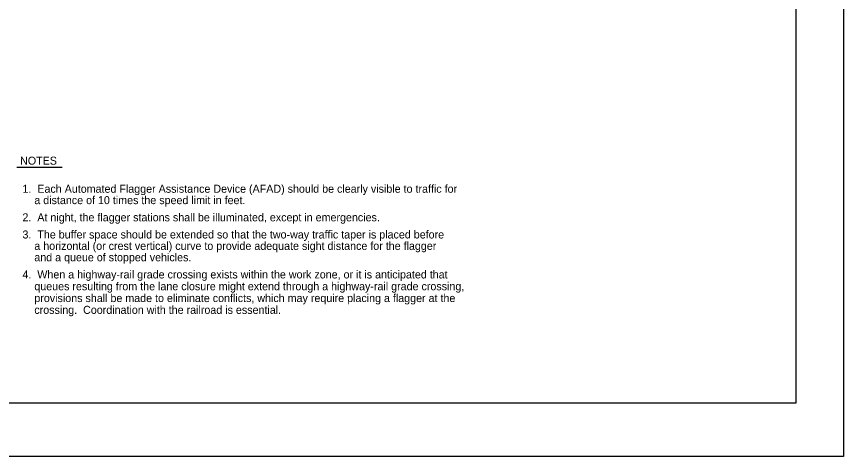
# Model space of a CAD drawing. Extents: x -14145 to -13662, y 30244 to 30661.
# Drawn here: x -13812.88 to -13791.17, y 30478.81 to 30490.36 of the extents above; entities that cross this region are included whole.
import ezdxf

# ---------------------------------------------------------------- set-up
doc = ezdxf.new("R2010")
doc.units = 0
for name, color, linetype in [('10', 7, 'Continuous'), ('2', 7, 'Continuous'), ('61', 7, 'Continuous')]:
    doc.layers.add(name, color=color, linetype=linetype)

msp = doc.modelspace()

# ---------------------------------------------------------------- linework, layer by layer
at = {"layer": '10'}
for p, q in [((-13792.422, 30502.777), (-13792.422, 30480.207)), ((-13792.422, 30480.207), (-13823.874, 30480.207))]:
    msp.add_line(p, q, dxfattribs=at)
at = {"layer": '2'}
msp.add_line((-13811.684, 30486.397), (-13812.875, 30486.397), dxfattribs=at)
at = {"layer": '61'}
msp.add_lwpolyline([(-13824.174, 30504.307), (-13791.174, 30504.307), (-13791.174, 30478.807), (-13824.174, 30478.807)], close=True, dxfattribs=at)

# ---------------------------------------------------------------- texts
at = {"layer": '2'}
for s, p in [('NOTES', (-13812.786, 30486.468)), ('1.  Each Automated Flagger Assistance Device (AFAD) should be clearly visible to traffic for ', (-13812.724, 30485.731)), ('    a distance of 10 times the speed limit in feet.', (-13812.724, 30485.432)), ('2.  At night, the flagger stations shall be illuminated, except in emergencies.', (-13812.724, 30484.981)), ('3.  The buffer space should be extended so that the two-way traffic taper is placed before ', (-13812.724, 30484.53)), ('    a horizontal (or crest vertical) curve to provide adequate sight distance for the flagger', (-13812.724, 30484.231)), ('    and a queue of stopped vehicles.', (-13812.724, 30483.932)), ('4.  When a highway-rail grade crossing exists within the work zone, or it is anticipated that ', (-13812.724, 30483.481)), ('    queues resulting from the lane closure might extend through a highway-rail grade crossing, ', (-13812.724, 30483.171)), ('    provisions shall be made to eliminate conflicts, which may require placing a flagger at the ', (-13812.724, 30482.861)), ('    crossing.  Coordination with the railroad is essential.', (-13812.724, 30482.551))]:
    msp.add_text(s, height=0.21, dxfattribs=at).set_placement(p)

doc.saveas('drawing.dxf')
